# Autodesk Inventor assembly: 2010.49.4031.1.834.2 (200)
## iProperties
Category: PARTsolutions
Created: 2012-10
Part Number: 2010.49.4031.1.834.2 (200)
Catalog Web Link: www.cadenas.de
Description: 2010. - Die Set similar DIN 9868/ISO 11415
Document SubType Name: Assembly
Designer: PARTsolutions
NB: 2010.49.4031.1.834.2 (200)
NN: 2010.
NT: Die Set similar DIN 9868/ISO 11415
NBSYN: 2010.$PW.$BF..$AMBC..$PK..$FA.$ZP..$LAF. ($SL.)
LINA: 2010.49.4031.1.834.2
ROWDESC: 2010.49.4031.1.834.2
PSOL_MULTISOLIDPART: 0.0
DOC: 2010_4x_6x_pdf
BF: 9
PW: 4
AM: 400x315
AF: 250x315
PK: 1
FA: 83
LAF: 2
ZP: 4
SL: 200
A1: 400.000
B1: 315.000
A2: 250.000
A3: 165.000
A4: 240.000
C1: 50.000
C2: 50.000
C3: 0.000
C4: 45.000
C5: 0.000
E1: 310.000
D1: 30.000
D2: 32.000
D3: 48.000
E2: 225.000
E3: 270.000
E4: 313.000
SLINHALT: 200,224,250,280,315,355,400,450,500
BFINHALT: '5','2 Saeulen mittig', '6','2 Saeulen diagonal', '7','2 Saeulen hinten', '9','4 Saeulen'
ZPZ: 4.000
PPATH: 2010_asmsbl.prj
AMBC: 4031
PKINHALT: '1','dick-dick','2','dick-duenn','3','duenn-dick','4','duenn-duenn'
LAFINHALT: '1','laengs','2','quer'
ZPINHALT: '4','ohne','5','mit'
KT: X
CreationOption_UseAsmMates: false
SUPPLIER: FIBRO
ARTICLENO: 2010.49.4031.1.834.2 (200)
BOMINFO: 2010.49.4031.1.834.2
CREATOR: CADENAS GmbH
PSOL_IDENT_0: {\\10.0.0.251\data_v9\23d-libs\fibro\normalien\a\a02\2010_asmtab.prj},216 {VTYP=3D},{STYP=ASSTAB},{N
PSOL_IDENT_1: B=2010.49.4031.1.834.2 (200)},{LINA=2010.49.4031.1.834.2},{NN=2010.},{DATE=10.05.2012 07:32:44},{GEO
PSOL_IDENT_2: MDATE=22.03.2012},{VERSION=v1},{LINEID=180},{LINESUBID=-1},{WBVAR=BF,PW,PK,FA,LAF,ZP,SL}  {NB=2010.4
PSOL_IDENT_3: 9.4031.1.834.2 (200)},{LINA=2010.49.4031.1.834.2},{KT=X},{DOC=2010_4x_6x_pdf},{BF=9},{PW=4},{AM=400x
PSOL_IDENT_4: 315},{AF=250x315},{PK=1},{FA=83},{LAF=2},{ZP=4},{SL=200},{A1=400.000},{B1=315.000},{A2=250.000},{A3=
PSOL_IDENT_5: 165.000},{A4=240.000},{C1=50},{C2=50},{C3=0},{C4=45},{C5=0},{E1=310.000},{D1=30.000},{D2=32.000},{D3
PSOL_IDENT_6: =48.000},{E2=225.000},{E3=270.000},{E4=313.000},{SLINHALT=200,224,250,280,315,355,400,450,500},{BFIN
PSOL_IDENT_7: HALT='5','2 Saeulen mittig', '6','2 Saeulen diagonal', '7','2 Saeulen hinten', '9','4 Saeulen'},{ZPZ
PSOL_IDENT_8: =4},{PPATH=2010_asmsbl.prj},{AMBC=4031},{PKINHALT='1','dick-dick','2','dick-duenn','3','duenn-dick',
PSOL_IDENT_9: '4','duenn-duenn'},{LAFINHALT='1','laengs','2','quer'},{ZPINHALT='4','ohne','5','mit'}
ipwModelExtentsX: 401.5
ipwModelExtentsY: 259.8
ipwModelExtentsZ: 315
ipwMass: 13.1
ipwArea: 0.9 m^2
ipwVolume: 13.1
Title: 2010.49.4031.1.834.2
Author: Cadenas PARTsolutions
Comments: Die Set similar DIN 9868/ISO 11415
